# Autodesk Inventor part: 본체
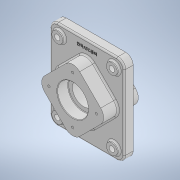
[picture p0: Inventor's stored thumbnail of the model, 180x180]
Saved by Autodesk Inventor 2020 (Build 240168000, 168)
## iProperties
Created: 2021-07
Part Number: 본체
Material: 일반
Document SubType Name: Modeling
Designer: Owner
Density: 1 g/cm^3
Appearance: 기본값
Mass: 807.977 g
Surface Area: 961.758 cm^2
Volume: 807.977 cm^3
Author: Owner
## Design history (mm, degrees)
sketch "스케치1"
  geometry: L1 (-75, -90)-(75, -90); L2 (75, -90)-(75, 90); L3 (75, 90)-(-75, 90); L4 (-75, 90)-(-75, -90); L5 (-75, -90)-(75, 90); L6 (75, -90)-(-75, 90); 1 further point
  constraints: 12 end point, 2 midpoint, 2 parallel, 1 horizontal, 1 perpendicular
  dimensions: "d0" = 150 distance of L3.end L2.end; "d1" = 180 distance of L2.end L1.end
extrude "돌출1" new body sketch "스케치1" stored distance "d2" = 18; taper "d3" = 0 deg
fillet "모깎기1" dims "d4" = 15
sketch "스케치2"
  geometry: L1 (0, -70.711)-(70.711, 0); L2 (70.711, 0)-(0, 70.711); L3 (0, 70.711)-(-70.711, 0); L4 (-70.711, 0)-(0, -70.711); L5 (0, -70.711)-(0, 70.711); L6 (70.711, 0)-(-70.711, 0); 2 further points
  constraints: 12 end point, 3 midpoint, 2 parallel, 1 perpendicular, 1 vertical alignment
  dimensions: "d5" = 100 distance of L1.end L2.end; "d6" = 100 distance of L1.start L1.end
extrude "돌출2" join sketch "스케치2" distance "d7" = 23; taper "d8" = 0 deg
sketch "스케치3"
  geometry: L1 (0, 70.711)-(-70.711, 0) reference; L2 (70.711, 0)-(0, 70.711) reference; L3 (0, -70.711)-(70.711, 0) reference; L4 (-70.711, 0)-(0, -70.711) reference; 1 further point
extrude "돌출3" join sketch "스케치3" distance "d9" = 29; taper "d10" = 0 deg
sketch "스케치4"
  geometry: C1 r 31 at (0, 0); 2 further points
  constraints: 2 coincident, 1 centre point
  dimensions: "d11" = 62 diameter of C1
extrude "돌출4" cut sketch "스케치4" distance "d12" = 22; taper "d13" = 0 deg
sketch "스케치5"
  geometry: C1 r 31 at (0, 0) reference; 1 further point
extrude "돌출5" cut sketch "스케치5" distance "d14" = 22; taper "d15" = 0 deg
fillet "모깎기2" dims "d16" = 20
sketch "스케치6"
  geometry: 2 further points
  constraints: 1 vertical alignment
  dimensions: "d17" = 48 distance of point (0, 0) point (0, 48)
hole "구멍1" sketch "스케치6" at (0, 48) diameter "d18" = 4.917; stored, may be unused: countersink angle "d22" = 90 deg, drill point angle "d24" = 118 deg; dims "d19" = 10, "d20" = 4, "d21" = 2, "d23" = 13
sketch "스케치7"
  geometry: 2 further points
  constraints: 1 vertical alignment
  dimensions: "d28" = 48 distance of point (0, 0) point (0, 48)
hole "구멍2" sketch "스케치7" at (0, 48) diameter "d29" = 4.917; stored, may be unused: countersink angle "d33" = 90 deg, drill point angle "d35" = 118 deg; dims "d30" = 10, "d31" = 4, "d32" = 2, "d34" = 13
sketch "스케치10"
  geometry: C1 r 31 at (0, 0) reference; C2 r 22.5 at (0, 0); 1 further point
  constraints: 1 centre point, 1 coincident
  dimensions: "d49" = 45 diameter of C2
extrude "돌출7" cut sketch "스케치10" extent not by distance; stored distance "d50" = 22; taper "d51" = 0 deg
sketch "스케치11"
  geometry: L1 (60, 90)-(-60, 90) reference; 2 further points
  constraints: 1 vertical alignment, 1 other
  dimensions: "d52" = 15 distance from line of L1 point (0, 75)
feature "엠보싱1" sketch "스케치11" dims "d0" = 150, "d1" = 180, "d53" = 0.5, "d54" = 0
chamfer "모따기1" distance "d55" = 1; stored, may be unused: second distance "d56" = 2, angle "d57" = 45 deg
fillet "모깎기3" dims "d58" = 1
fillet "모깎기5" dims "d60" = 3
fillet "모깎기6" dims "d61" = 3
fillet "모깎기7" dims "d62" = 3
sketch "스케치12"
  geometry: C1 r 11 at (-55, 70); 1 further point
  constraints: 1 centre point
  dimensions: "d63" = 22 diameter of C1; "d64" = 70 vertical distance of point (0, 0) C1.centre; "d65" = 55 horizontal distance of point (0, 0) C1.centre
extrude "돌출8" join sketch "스케치12" distance "d66" = 5; taper "d67" = 0 deg
sketch "스케치13"
  geometry: C1 r 11 at (0, 0) reference; 2 further points
  constraints: 1 coincident
hole "구멍4" sketch "스케치13" at (0, 0) diameter "d68" = 11; stored, may be unused: countersink angle "d72" = 90 deg, drill point angle "d74" = 118 deg; dims "d69" = 10, "d70" = 4, "d71" = 2, "d73" = 13
fillet "모깎기8" dims "d75" = 3
node "솔리드1"
pattern_circular "원형 패턴1" dims angle "d26" = 360 deg
pattern_circular "원형 패턴2" dims angle "d37" = 360 deg
mirror "미러4"
mirror "미러5"
feature "A9D066F2-1C7D-4E18-AEED-F7BC21143FA4" dims "d68" = 11, "d69" = 10, "d70" = 4, "d71" = 2, "d72" = 90 deg, "d73" = 13, "d74" = 118 deg
